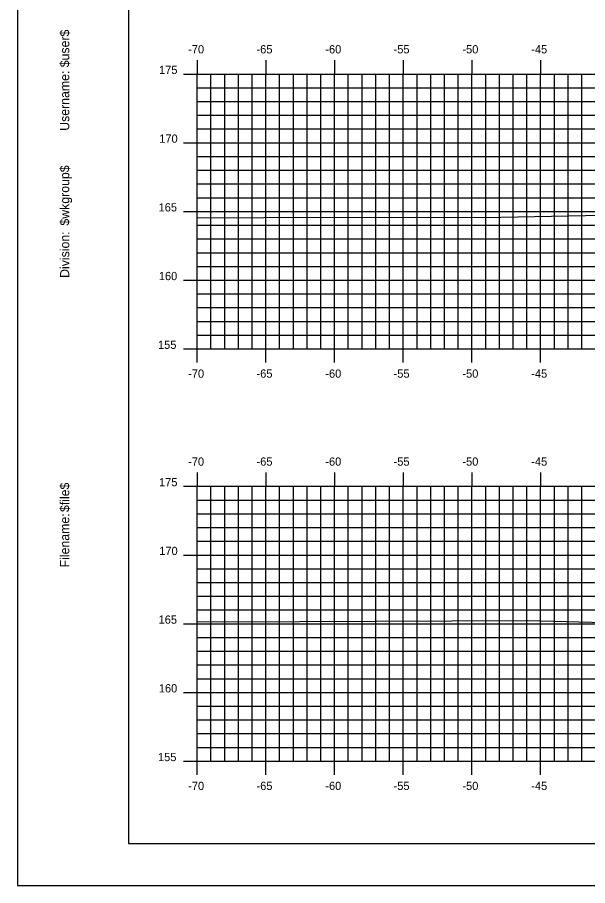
# Model space of a CAD drawing. Extents: x 1142755 to 1142925, y 608981 to 609091.
# Drawn here: x 1142754.7 to 1142796.2, y 608981.3 to 609044.5 of the extents above; entities that cross this region are included whole.
import ezdxf

# ---------------------------------------------------------------- set-up
doc = ezdxf.new("R2010")
doc.units = 0
for name, color, linetype in [('BORDER', 7, 'Continuous'), ('H_V ANNOTATION', 7, 'Continuous'), ('MAJOR', 7, 'Continuous'), ('MINOR', 7, 'Continuous'), ('PLOT BOUNDARY', 7, 'Continuous'), ('S_Roadway_Centerline', 7, 'Continuous')]:
    doc.layers.add(name, color=color, linetype=linetype)

msp = doc.modelspace()

# ---------------------------------------------------------------- linework, layer by layer
at = {"layer": 'BORDER'}
msp.add_lwpolyline([(1142762.81, 608984.335), (1142922.81, 608984.335), (1142922.81, 609089.335), (1142762.81, 609089.335)], close=True, dxfattribs=at)
at = {"layer": 'MAJOR'}
for p, q in [((1142767.81, 609041.337), (1142767.81, 609040.335)), ((1142772.81, 609041.337), (1142772.81, 609040.335)), ((1142777.81, 609041.337), (1142777.81, 609040.335)), ((1142782.81, 609041.337), (1142782.81, 609040.335)), ((1142787.81, 609041.337), (1142787.81, 609040.335)), ((1142792.81, 609041.337), (1142792.81, 609040.335)), ((1142766.808, 609040.335), (1142767.81, 609040.335)), ((1142767.81, 609040.335), (1142907.81, 609040.335)), ((1142767.81, 609020.335), (1142767.81, 609040.335)), ((1142767.81, 609020.335), (1142767.81, 609040.335)), ((1142767.81, 609040.335), (1142907.81, 609040.335)), ((1142772.81, 609020.335), (1142772.81, 609040.335)), ((1142777.81, 609020.335), (1142777.81, 609040.335)), ((1142782.81, 609020.335), (1142782.81, 609040.335)), ((1142787.81, 609020.335), (1142787.81, 609040.335)), ((1142792.81, 609020.335), (1142792.81, 609040.335)), ((1142766.808, 609035.335), (1142767.81, 609035.335)), ((1142767.81, 609035.335), (1142907.81, 609035.335)), ((1142766.808, 609030.335), (1142767.81, 609030.335)), ((1142767.81, 609030.335), (1142907.81, 609030.335)), ((1142766.808, 609025.335), (1142767.81, 609025.335)), ((1142767.81, 609025.335), (1142907.81, 609025.335)), ((1142766.808, 609020.335), (1142767.81, 609020.335)), ((1142767.81, 609020.335), (1142907.81, 609020.335)), ((1142767.81, 609020.335), (1142907.81, 609020.335)), ((1142767.81, 609019.333), (1142767.81, 609020.335)), ((1142772.81, 609019.333), (1142772.81, 609020.335)), ((1142777.81, 609019.333), (1142777.81, 609020.335)), ((1142782.81, 609019.333), (1142782.81, 609020.335)), ((1142787.81, 609019.333), (1142787.81, 609020.335)), ((1142792.81, 609019.333), (1142792.81, 609020.335)), ((1142767.81, 609011.337), (1142767.81, 609010.335)), ((1142772.81, 609011.337), (1142772.81, 609010.335)), ((1142777.81, 609011.337), (1142777.81, 609010.335)), ((1142782.81, 609011.337), (1142782.81, 609010.335)), ((1142787.81, 609011.337), (1142787.81, 609010.335)), ((1142792.81, 609011.337), (1142792.81, 609010.335)), ((1142766.808, 609010.335), (1142767.81, 609010.335)), ((1142767.81, 609010.335), (1142907.81, 609010.335)), ((1142767.81, 608990.335), (1142767.81, 609010.335)), ((1142767.81, 608990.335), (1142767.81, 609010.335)), ((1142767.81, 609010.335), (1142907.81, 609010.335)), ((1142772.81, 608990.335), (1142772.81, 609010.335)), ((1142777.81, 608990.335), (1142777.81, 609010.335)), ((1142782.81, 608990.335), (1142782.81, 609010.335)), ((1142787.81, 608990.335), (1142787.81, 609010.335)), ((1142792.81, 608990.335), (1142792.81, 609010.335)), ((1142766.808, 609005.335), (1142767.81, 609005.335)), ((1142767.81, 609005.335), (1142907.81, 609005.335)), ((1142766.808, 609000.335), (1142767.81, 609000.335)), ((1142767.81, 609000.335), (1142907.81, 609000.335)), ((1142766.808, 608995.335), (1142767.81, 608995.335)), ((1142767.81, 608995.335), (1142907.81, 608995.335)), ((1142766.808, 608990.335), (1142767.81, 608990.335)), ((1142767.81, 608990.335), (1142907.81, 608990.335)), ((1142767.81, 608990.335), (1142907.81, 608990.335)), ((1142767.81, 608989.333), (1142767.81, 608990.335)), ((1142772.81, 608989.333), (1142772.81, 608990.335)), ((1142777.81, 608989.333), (1142777.81, 608990.335)), ((1142782.81, 608989.333), (1142782.81, 608990.335)), ((1142787.81, 608989.333), (1142787.81, 608990.335)), ((1142792.81, 608989.333), (1142792.81, 608990.335))]:
    msp.add_line(p, q, dxfattribs=at)
at = {"layer": 'MINOR'}
for p, q in [((1142768.81, 609020.335), (1142768.81, 609040.335)), ((1142769.81, 609020.335), (1142769.81, 609040.335)), ((1142770.81, 609020.335), (1142770.81, 609040.335)), ((1142771.81, 609020.335), (1142771.81, 609040.335)), ((1142773.81, 609020.335), (1142773.81, 609040.335)), ((1142774.81, 609020.335), (1142774.81, 609040.335)), ((1142775.81, 609020.335), (1142775.81, 609040.335)), ((1142776.81, 609020.335), (1142776.81, 609040.335)), ((1142778.81, 609020.335), (1142778.81, 609040.335)), ((1142779.81, 609020.335), (1142779.81, 609040.335)), ((1142780.81, 609020.335), (1142780.81, 609040.335)), ((1142781.81, 609020.335), (1142781.81, 609040.335)), ((1142783.81, 609020.335), (1142783.81, 609040.335)), ((1142784.81, 609020.335), (1142784.81, 609040.335)), ((1142785.81, 609020.335), (1142785.81, 609040.335)), ((1142786.81, 609020.335), (1142786.81, 609040.335)), ((1142788.81, 609020.335), (1142788.81, 609040.335)), ((1142789.81, 609020.335), (1142789.81, 609040.335)), ((1142790.81, 609020.335), (1142790.81, 609040.335)), ((1142791.81, 609020.335), (1142791.81, 609040.335)), ((1142793.81, 609020.335), (1142793.81, 609040.335)), ((1142794.81, 609020.335), (1142794.81, 609040.335)), ((1142795.81, 609020.335), (1142795.81, 609040.335)), ((1142767.81, 609039.335), (1142907.81, 609039.335)), ((1142767.81, 609039.335), (1142768.812, 609039.335)), ((1142767.81, 609038.335), (1142907.81, 609038.335)), ((1142767.81, 609038.335), (1142768.812, 609038.335)), ((1142767.81, 609037.335), (1142907.81, 609037.335)), ((1142767.81, 609037.335), (1142768.812, 609037.335)), ((1142767.81, 609036.335), (1142907.81, 609036.335)), ((1142767.81, 609036.335), (1142768.812, 609036.335)), ((1142767.81, 609034.335), (1142907.81, 609034.335)), ((1142767.81, 609034.335), (1142768.812, 609034.335)), ((1142767.81, 609033.335), (1142907.81, 609033.335)), ((1142767.81, 609033.335), (1142768.812, 609033.335)), ((1142767.81, 609032.335), (1142907.81, 609032.335)), ((1142767.81, 609032.335), (1142768.812, 609032.335)), ((1142767.81, 609031.335), (1142907.81, 609031.335)), ((1142767.81, 609031.335), (1142768.812, 609031.335)), ((1142767.81, 609029.335), (1142907.81, 609029.335)), ((1142767.81, 609029.335), (1142768.812, 609029.335)), ((1142767.81, 609028.335), (1142907.81, 609028.335)), ((1142767.81, 609028.335), (1142768.812, 609028.335)), ((1142767.81, 609027.335), (1142907.81, 609027.335)), ((1142767.81, 609027.335), (1142768.812, 609027.335)), ((1142767.81, 609026.335), (1142907.81, 609026.335)), ((1142767.81, 609026.335), (1142768.812, 609026.335)), ((1142767.81, 609024.335), (1142907.81, 609024.335)), ((1142767.81, 609024.335), (1142768.812, 609024.335)), ((1142767.81, 609023.335), (1142907.81, 609023.335)), ((1142767.81, 609023.335), (1142768.812, 609023.335)), ((1142767.81, 609022.335), (1142907.81, 609022.335)), ((1142767.81, 609022.335), (1142768.812, 609022.335)), ((1142767.81, 609021.335), (1142907.81, 609021.335)), ((1142767.81, 609021.335), (1142768.812, 609021.335)), ((1142768.81, 608990.335), (1142768.81, 609010.335)), ((1142769.81, 608990.335), (1142769.81, 609010.335)), ((1142770.81, 608990.335), (1142770.81, 609010.335)), ((1142771.81, 608990.335), (1142771.81, 609010.335)), ((1142773.81, 608990.335), (1142773.81, 609010.335)), ((1142774.81, 608990.335), (1142774.81, 609010.335)), ((1142775.81, 608990.335), (1142775.81, 609010.335)), ((1142776.81, 608990.335), (1142776.81, 609010.335)), ((1142778.81, 608990.335), (1142778.81, 609010.335)), ((1142779.81, 608990.335), (1142779.81, 609010.335)), ((1142780.81, 608990.335), (1142780.81, 609010.335)), ((1142781.81, 608990.335), (1142781.81, 609010.335)), ((1142783.81, 608990.335), (1142783.81, 609010.335)), ((1142784.81, 608990.335), (1142784.81, 609010.335)), ((1142785.81, 608990.335), (1142785.81, 609010.335)), ((1142786.81, 608990.335), (1142786.81, 609010.335)), ((1142788.81, 608990.335), (1142788.81, 609010.335)), ((1142789.81, 608990.335), (1142789.81, 609010.335)), ((1142790.81, 608990.335), (1142790.81, 609010.335)), ((1142791.81, 608990.335), (1142791.81, 609010.335)), ((1142793.81, 608990.335), (1142793.81, 609010.335)), ((1142794.81, 608990.335), (1142794.81, 609010.335)), ((1142795.81, 608990.335), (1142795.81, 609010.335)), ((1142767.81, 609009.335), (1142907.81, 609009.335)), ((1142767.81, 609009.335), (1142768.812, 609009.335)), ((1142767.81, 609008.335), (1142907.81, 609008.335)), ((1142767.81, 609008.335), (1142768.812, 609008.335)), ((1142767.81, 609007.335), (1142907.81, 609007.335)), ((1142767.81, 609007.335), (1142768.812, 609007.335)), ((1142767.81, 609006.335), (1142907.81, 609006.335)), ((1142767.81, 609006.335), (1142768.812, 609006.335)), ((1142767.81, 609004.335), (1142907.81, 609004.335)), ((1142767.81, 609004.335), (1142768.812, 609004.335)), ((1142767.81, 609003.335), (1142907.81, 609003.335)), ((1142767.81, 609003.335), (1142768.812, 609003.335)), ((1142767.81, 609002.335), (1142907.81, 609002.335)), ((1142767.81, 609002.335), (1142768.812, 609002.335)), ((1142767.81, 609001.335), (1142907.81, 609001.335)), ((1142767.81, 609001.335), (1142768.812, 609001.335)), ((1142767.81, 608999.335), (1142907.81, 608999.335)), ((1142767.81, 608999.335), (1142768.812, 608999.335)), ((1142767.81, 608998.335), (1142907.81, 608998.335)), ((1142767.81, 608998.335), (1142768.812, 608998.335)), ((1142767.81, 608997.335), (1142907.81, 608997.335)), ((1142767.81, 608997.335), (1142768.812, 608997.335)), ((1142767.81, 608996.335), (1142907.81, 608996.335)), ((1142767.81, 608996.335), (1142768.812, 608996.335)), ((1142767.81, 608994.335), (1142907.81, 608994.335)), ((1142767.81, 608994.335), (1142768.812, 608994.335)), ((1142767.81, 608993.335), (1142907.81, 608993.335)), ((1142767.81, 608993.335), (1142768.812, 608993.335)), ((1142767.81, 608992.335), (1142907.81, 608992.335)), ((1142767.81, 608992.335), (1142768.812, 608992.335)), ((1142767.81, 608991.335), (1142907.81, 608991.335)), ((1142767.81, 608991.335), (1142768.812, 608991.335))]:
    msp.add_line(p, q, dxfattribs=at)
at = {"layer": 'PLOT BOUNDARY'}
msp.add_lwpolyline([(1142754.717, 608981.276), (1142924.717, 608981.276), (1142924.717, 609091.276), (1142754.717, 609091.276)], close=True, dxfattribs=at)
at = {"layer": 'S_Roadway_Centerline'}
for points in [[(1142767.81, 609029.872), (1142772.659, 609029.903), (1142789.902, 609029.91), (1142803.459, 609030.179), (1142813.124, 609029.964), (1142815.249, 609029.282), (1142818.76, 609028.26), (1142819.78, 609028.76), (1142821.467, 609029.225), (1142823.377, 609029.407), (1142824.778, 609029.469), (1142824.866, 609029.472), (1142829.375, 609029.546), (1142836.25, 609029.718), (1142841.052, 609029.61), (1142846.97, 609029.506), (1142848.923, 609029.281), (1142851.479, 609029.02), (1142852.506, 609028.667), (1142853.62, 609028.219)], [(1142767.81, 609000.492), (1142769.72, 609000.472), (1142791.868, 609000.571), (1142801.171, 609000.338), (1142812.704, 609000.117), (1142813.716, 609000.114), (1142816.434, 609000.342), (1142817.916, 609000.395), (1142819.044, 609000.26), (1142821.193, 609000.108), (1142822.89, 609000.096), (1142824.694, 609000.064), (1142830.108, 609000.149), (1142835.615, 609000.249), (1142838.206, 609000.162), (1142846.754, 608999.969), (1142847.489, 608999.907), (1142850.927, 608999.511), (1142851.828, 608999.305), (1142853.607, 608998.697)]]:
    msp.add_lwpolyline(points, dxfattribs=at)

# ---------------------------------------------------------------- texts
at = {"layer": 'BORDER'}
for s, p in [('$user$', (1142758.495, 609040.827)), ('Username:', (1142758.495, 609036.203)), ('$wkgroup$', (1142758.495, 609029.305)), ('Division:', (1142758.495, 609025.501)), ('$file$', (1142758.495, 609008.461)), ('Filename:', (1142758.495, 609004.433))]:
    msp.add_text(s, height=0.6696, rotation=90, dxfattribs=at).set_placement(p)
at = {"layer": 'H_V ANNOTATION'}
for s, p in [('-70', (1142767.152, 609041.835)), ('-65', (1142772.128, 609041.835)), ('-60', (1142777.136, 609041.835)), ('-55', (1142782.106, 609041.835)), ('-50', (1142787.114, 609041.835)), ('-45', (1142792.128, 609041.835)), ('175', (1142765.031, 609040.335)), ('170', (1142765.047, 609035.335)), ('165', (1142764.999, 609030.335)), ('160', (1142765.015, 609025.335)), ('155', (1142764.956, 609020.335)), ('-70', (1142767.152, 609018.235)), ('-65', (1142772.128, 609018.235)), ('-60', (1142777.136, 609018.235)), ('-55', (1142782.106, 609018.235)), ('-50', (1142787.114, 609018.235)), ('-45', (1142792.128, 609018.235)), ('-70', (1142767.152, 609011.835)), ('-65', (1142772.128, 609011.835)), ('-60', (1142777.136, 609011.835)), ('-55', (1142782.106, 609011.835)), ('-50', (1142787.114, 609011.835)), ('-45', (1142792.128, 609011.835)), ('175', (1142765.031, 609010.335)), ('170', (1142765.047, 609005.335)), ('165', (1142764.999, 609000.335)), ('160', (1142765.015, 608995.335)), ('155', (1142764.956, 608990.335)), ('-70', (1142767.152, 608988.235)), ('-65', (1142772.128, 608988.235)), ('-60', (1142777.136, 608988.235)), ('-55', (1142782.106, 608988.235)), ('-50', (1142787.114, 608988.235)), ('-45', (1142792.128, 608988.235))]:
    msp.add_text(s, height=0.6, dxfattribs=at).set_placement(p)
at = {"layer": 'MAJOR'}
for p in [(1142767.806, 609020.335), (1142767.806, 608990.335)]:
    msp.add_text('-', height=0.006, dxfattribs=at).set_placement(p)

doc.saveas('drawing.dxf')
